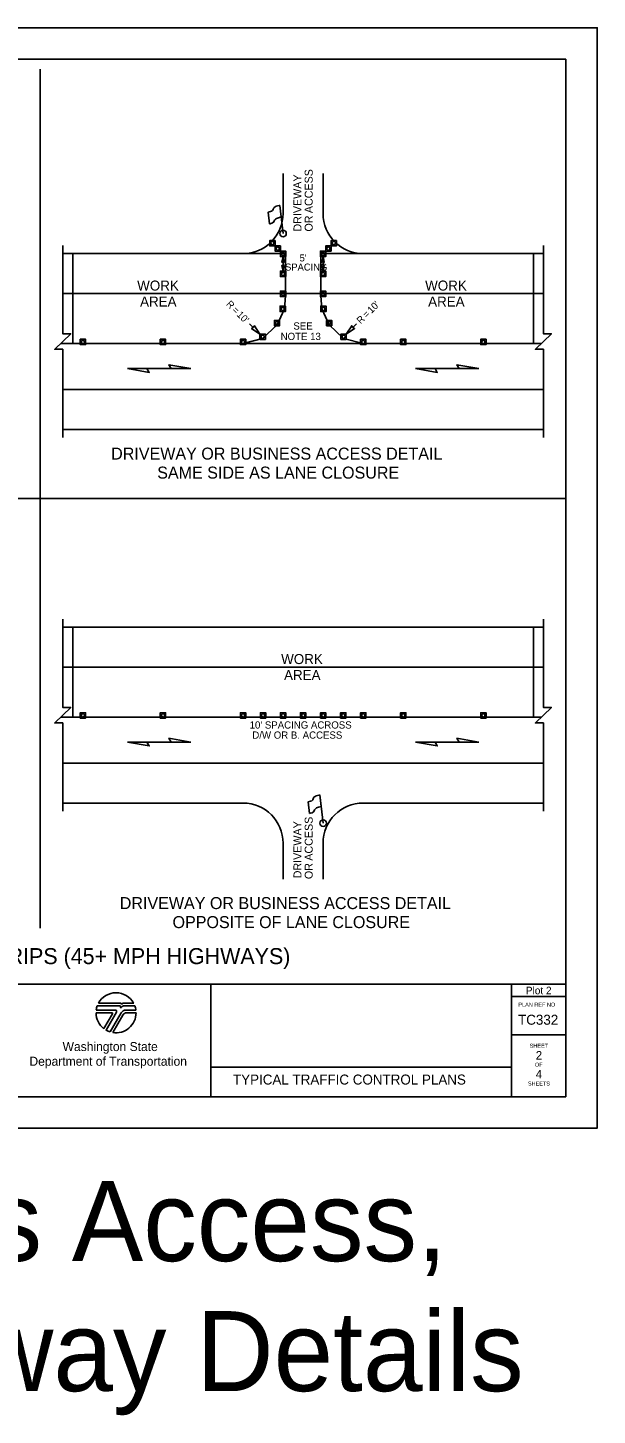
# Model space of a CAD drawing. Extents: x 99999.1 to 100095.7, y 99995 to 100010.7.
# Drawn here: x 100030.38 to 100036.06, y 99996.82 to 100010.69 of the extents above; entities that cross this region are included whole.
import ezdxf

# ---------------------------------------------------------------- set-up
doc = ezdxf.new("R2010")
doc.units = 0
for name, color, linetype in [('RD_ED_DrivewayEdge', 7, 'Continuous'), ('RD_ED_ShoulderPavedEdge', 7, 'Continuous'), ('RD_MK_LineEdgeWhite', 7, 'Continuous'), ('RD_MK_LineSkipCenter', 7, 'Continuous'), ('SH_DE_DetailHeading1Text', 7, 'Continuous'), ('SH_DE_DetailHeading2Text', 7, 'Continuous'), ('SH_GI_PlotLimits', 7, 'Continuous'), ('SH_GI_SheetBorder', 7, 'Continuous'), ('SH_GI_SheetLocationText', 7, 'Continuous'), ('SH_GI_SheetTextInCells', 7, 'Continuous'), ('SH_GI_TitleBlockText', 7, 'Continuous'), ('SH_GI_WSDOTLogo', 7, 'Continuous'), ('TR_WZ_FlaggingStation', 7, 'Continuous'), ('TR_WZ_TrafficCone', 7, 'Continuous'), ('TR_WZ_WorkAreaLabel', 7, 'Continuous'), ('TR_WZ_WorkZoneDetails', 7, 'Continuous'), ('TR_WZ_WorkZoneTextCurrent', 7, 'Continuous')]:
    doc.layers.add(name, color=color, linetype=linetype)

msp = doc.modelspace()

# ---------------------------------------------------------------- linework, layer by layer
at = {"layer": 'RD_ED_DrivewayEdge'}
for p, q in [((100032.925, 100008.83), (100032.925, 100009.23)), ((100033.325, 100008.83), (100033.325, 100009.23)), ((100032.925, 100002.536), (100032.925, 100002.176)), ((100033.325, 100002.536), (100033.325, 100002.176))]:
    msp.add_line(p, q, dxfattribs=at)
for centre, start, end in [((100032.525, 100008.83), 270, 0), ((100033.725, 100008.83), 180, 270), ((100032.525, 100002.536), 0, 90), ((100033.725, 100002.536), 90, 180)]:
    msp.add_arc(centre, 0.4, start, end, dxfattribs=at)
at = {"layer": 'RD_ED_ShoulderPavedEdge'}
for p, q in [((100030.725, 100008.43), (100032.525, 100008.43)), ((100033.725, 100008.43), (100035.525, 100008.43)), ((100030.725, 100006.67), (100035.525, 100006.67)), ((100030.725, 100004.696), (100035.525, 100004.696)), ((100030.725, 100002.936), (100032.525, 100002.936)), ((100033.725, 100002.936), (100035.525, 100002.936))]:
    msp.add_line(p, q, dxfattribs=at)
at = {"layer": 'RD_MK_LineEdgeWhite'}
for p, q in [((100030.725, 100008.03), (100035.525, 100008.03)), ((100030.725, 100007.07), (100035.525, 100007.07)), ((100030.725, 100004.296), (100035.525, 100004.296)), ((100030.725, 100003.336), (100035.525, 100003.336))]:
    msp.add_line(p, q, dxfattribs=at)
at = {"layer": 'RD_MK_LineSkipCenter'}
for points in [[(100035.504, 100007.53), (100030.704, 100007.53)], [(100035.504, 100003.796), (100030.704, 100003.796)]]:
    msp.add_lwpolyline(points, dxfattribs=at)
at = {"layer": 'SH_GI_PlotLimits'}
msp.add_lwpolyline([(100019.062, 99999.687), (100036.062, 99999.687), (100036.062, 100010.687), (100019.062, 100010.687)], close=True, dxfattribs=at)
at = {"layer": 'SH_GI_SheetBorder'}
for p, q in [((100020, 100010.375), (100035.75, 100010.375)), ((100035.75, 100010.375), (100035.75, 100000)), ((100020, 100001.126), (100035.75, 100001.126)), ((100032.205, 100001.126), (100032.205, 100000)), ((100035.208, 100001.126), (100035.208, 100000)), ((100035.208, 100001.001), (100035.75, 100001.001)), ((100035.208, 100000.618), (100035.75, 100000.618)), ((100032.205, 100000.295), (100035.208, 100000.295)), ((100020, 100000), (100035.75, 100000))]:
    msp.add_line(p, q, dxfattribs=at)
at = {"layer": 'SH_GI_WSDOTLogo'}
for p, q in [((100031.059, 100000.866), (100031.25, 100000.866)), ((100031.289, 100000.909), (100031.07, 100000.909)), ((100031.303, 100000.935), (100031.081, 100000.935)), ((100031.433, 100000.935), (100031.335, 100000.935)), ((100031.445, 100000.909), (100031.343, 100000.909)), ((100031.343, 100000.909), (100031.343, 100000.909)), ((100031.356, 100000.866), (100031.456, 100000.866)), ((100031.057, 100000.84), (100031.215, 100000.84)), ((100031.222, 100000.828), (100031.136, 100000.681)), ((100031.261, 100000.846), (100031.157, 100000.667)), ((100031.199, 100000.649), (100031.309, 100000.839)), ((100031.224, 100000.643), (100031.324, 100000.816)), ((100031.365, 100000.839), (100031.457, 100000.839))]:
    msp.add_line(p, q, dxfattribs=at)
for centre, radius, start, end in [((100031.257, 100000.84), 0.2, 28.4787, 151.532), ((100031.257, 100000.84), 0.2, 159.696, 172.5057), ((100031.25, 100000.853), 0.0131, 329.7683, 90), ((100031.289, 100000.895), 0.0148, 327.8418, 89.9985), ((100031.343, 100000.861), 0.0484, 89.9953, 147.8238), ((100031.303, 100000.926), 0.00903, 329.8742, 90.0033), ((100031.356, 100000.812), 0.0542, 90, 149.9974), ((100031.335, 100000.907), 0.0287, 90.0072, 148.1676), ((100031.257, 100000.84), 0.2, 7.4943, 20.2941), ((100031.257, 100000.84), 0.2, 179.9986, 232.8433), ((100031.215, 100000.832), 0.0082, 329.7436, 90), ((100031.257, 100000.84), 0.2, 260.5455, 359.8086), ((100031.365, 100000.792), 0.0476, 90, 150.0543), ((100031.257, 100000.84), 0.2, 239.7929, 253.0448)]:
    msp.add_arc(centre, radius, start, end, dxfattribs=at)
at = {"layer": 'TR_WZ_FlaggingStation'}
for p, q in [((100032.906, 100008.797), (100032.893, 100008.912)), ((100032.925, 100008.63), (100032.893, 100008.911)), ((100032.775, 100008.844), (100032.788, 100008.727)), ((100032.906, 100008.797), (100032.906, 100008.797)), ((100033.175, 100002.949), (100033.188, 100002.832)), ((100033.325, 100002.736), (100033.293, 100003.017)), ((100033.306, 100002.903), (100033.293, 100003.017)), ((100033.306, 100002.903), (100033.306, 100002.903))]:
    msp.add_line(p, q, dxfattribs=at)
for points in [[(100032.893, 100008.912), (100032.887, 100008.91), (100032.869, 100008.907), (100032.856, 100008.903), (100032.846, 100008.897), (100032.837, 100008.892), (100032.832, 100008.885), (100032.827, 100008.877), (100032.827, 100008.871), (100032.821, 100008.862), (100032.811, 100008.854), (100032.798, 100008.849), (100032.775, 100008.844)], [(100032.788, 100008.727), (100032.796, 100008.728), (100032.814, 100008.733), (100032.83, 100008.743), (100032.836, 100008.754), (100032.84, 100008.764), (100032.849, 100008.775), (100032.86, 100008.781), (100032.878, 100008.788), (100032.906, 100008.797)], [(100033.293, 100003.017), (100033.287, 100003.016), (100033.269, 100003.012), (100033.256, 100003.008), (100033.246, 100003.002), (100033.237, 100002.997), (100033.232, 100002.991), (100033.227, 100002.983), (100033.227, 100002.977), (100033.221, 100002.967), (100033.211, 100002.96), (100033.198, 100002.955), (100033.175, 100002.949)], [(100033.188, 100002.832), (100033.196, 100002.834), (100033.214, 100002.838), (100033.23, 100002.849), (100033.236, 100002.859), (100033.24, 100002.87), (100033.249, 100002.88), (100033.26, 100002.887), (100033.278, 100002.894), (100033.306, 100002.903)]]:
    msp.add_lwpolyline(points, dxfattribs=at)
for centre in [(100032.925, 100008.63), (100033.325, 100002.736)]:
    msp.add_circle(centre, 0.0325, dxfattribs=at)
at = {"layer": 'TR_WZ_TrafficCone'}
for points in [[(100032.845, 100008.56), (100032.845, 100008.507), (100032.792, 100008.507), (100032.792, 100008.56), (100032.845, 100008.56)], [(100032.792, 100008.56), (100032.792, 100008.507), (100032.845, 100008.507), (100032.845, 100008.56), (100032.792, 100008.56)], [(100032.898, 100008.507), (100032.898, 100008.454), (100032.845, 100008.454), (100032.845, 100008.507), (100032.898, 100008.507)], [(100032.845, 100008.507), (100032.845, 100008.454), (100032.898, 100008.454), (100032.898, 100008.507), (100032.845, 100008.507)], [(100033.352, 100008.507), (100033.352, 100008.454), (100033.405, 100008.454), (100033.405, 100008.507), (100033.352, 100008.507)], [(100033.405, 100008.507), (100033.405, 100008.454), (100033.352, 100008.454), (100033.352, 100008.507), (100033.405, 100008.507)], [(100033.405, 100008.56), (100033.405, 100008.507), (100033.458, 100008.507), (100033.458, 100008.56), (100033.405, 100008.56)], [(100033.458, 100008.56), (100033.458, 100008.507), (100033.405, 100008.507), (100033.405, 100008.56), (100033.458, 100008.56)], [(100032.898, 100008.454), (100032.952, 100008.454), (100032.952, 100008.4), (100032.898, 100008.4), (100032.898, 100008.454)], [(100032.898, 100008.4), (100032.952, 100008.4), (100032.952, 100008.454), (100032.898, 100008.454), (100032.898, 100008.4)], [(100033.352, 100008.454), (100033.298, 100008.454), (100033.298, 100008.4), (100033.352, 100008.4), (100033.352, 100008.454)], [(100033.352, 100008.4), (100033.298, 100008.4), (100033.298, 100008.454), (100033.352, 100008.454), (100033.352, 100008.4)], [(100032.898, 100008.254), (100032.952, 100008.254), (100032.952, 100008.2), (100032.898, 100008.2), (100032.898, 100008.254)], [(100032.898, 100008.2), (100032.952, 100008.2), (100032.952, 100008.254), (100032.898, 100008.254), (100032.898, 100008.2)], [(100033.352, 100008.254), (100033.298, 100008.254), (100033.298, 100008.2), (100033.352, 100008.2), (100033.352, 100008.254)], [(100033.352, 100008.2), (100033.298, 100008.2), (100033.298, 100008.254), (100033.352, 100008.254), (100033.352, 100008.2)], [(100032.898, 100008.054), (100032.952, 100008.054), (100032.952, 100008), (100032.898, 100008), (100032.898, 100008.054)], [(100032.898, 100008), (100032.952, 100008), (100032.952, 100008.054), (100032.898, 100008.054), (100032.898, 100008)], [(100033.352, 100008.054), (100033.298, 100008.054), (100033.298, 100008), (100033.352, 100008), (100033.352, 100008.054)], [(100033.352, 100008), (100033.298, 100008), (100033.298, 100008.054), (100033.352, 100008.054), (100033.352, 100008)], [(100032.896, 100007.904), (100032.949, 100007.904), (100032.949, 100007.85), (100032.896, 100007.85), (100032.896, 100007.904)], [(100032.896, 100007.85), (100032.949, 100007.85), (100032.949, 100007.904), (100032.896, 100007.904), (100032.896, 100007.85)], [(100033.354, 100007.904), (100033.301, 100007.904), (100033.301, 100007.85), (100033.354, 100007.85), (100033.354, 100007.904)], [(100033.354, 100007.85), (100033.301, 100007.85), (100033.301, 100007.904), (100033.354, 100007.904), (100033.354, 100007.85)], [(100032.838, 100007.762), (100032.891, 100007.762), (100032.891, 100007.708), (100032.838, 100007.708), (100032.838, 100007.762)], [(100032.838, 100007.708), (100032.891, 100007.708), (100032.891, 100007.762), (100032.838, 100007.762), (100032.838, 100007.708)], [(100033.412, 100007.762), (100033.359, 100007.762), (100033.359, 100007.708), (100033.412, 100007.708), (100033.412, 100007.762)], [(100033.412, 100007.708), (100033.359, 100007.708), (100033.359, 100007.762), (100033.412, 100007.762), (100033.412, 100007.708)], [(100030.899, 100007.574), (100030.952, 100007.574), (100030.952, 100007.52), (100030.899, 100007.52), (100030.899, 100007.574)], [(100030.899, 100007.52), (100030.952, 100007.52), (100030.952, 100007.574), (100030.899, 100007.574), (100030.899, 100007.52)], [(100031.699, 100007.574), (100031.752, 100007.574), (100031.752, 100007.52), (100031.699, 100007.52), (100031.699, 100007.574)], [(100031.699, 100007.52), (100031.752, 100007.52), (100031.752, 100007.574), (100031.699, 100007.574), (100031.699, 100007.52)], [(100032.499, 100007.574), (100032.552, 100007.574), (100032.552, 100007.52), (100032.499, 100007.52), (100032.499, 100007.574)], [(100032.499, 100007.52), (100032.552, 100007.52), (100032.552, 100007.574), (100032.499, 100007.574), (100032.499, 100007.52)], [(100032.694, 100007.625), (100032.748, 100007.625), (100032.748, 100007.571), (100032.694, 100007.571), (100032.694, 100007.625)], [(100032.694, 100007.571), (100032.748, 100007.571), (100032.748, 100007.625), (100032.694, 100007.625), (100032.694, 100007.571)], [(100033.556, 100007.625), (100033.502, 100007.625), (100033.502, 100007.571), (100033.556, 100007.571), (100033.556, 100007.625)], [(100033.556, 100007.571), (100033.502, 100007.571), (100033.502, 100007.625), (100033.556, 100007.625), (100033.556, 100007.571)], [(100033.699, 100007.574), (100033.752, 100007.574), (100033.752, 100007.52), (100033.699, 100007.52), (100033.699, 100007.574)], [(100033.699, 100007.52), (100033.752, 100007.52), (100033.752, 100007.574), (100033.699, 100007.574), (100033.699, 100007.52)], [(100034.099, 100007.574), (100034.152, 100007.574), (100034.152, 100007.52), (100034.099, 100007.52), (100034.099, 100007.574)], [(100034.099, 100007.52), (100034.152, 100007.52), (100034.152, 100007.574), (100034.099, 100007.574), (100034.099, 100007.52)], [(100034.899, 100007.574), (100034.952, 100007.574), (100034.952, 100007.52), (100034.899, 100007.52), (100034.899, 100007.574)], [(100034.899, 100007.52), (100034.952, 100007.52), (100034.952, 100007.574), (100034.899, 100007.574), (100034.899, 100007.52)], [(100030.899, 100003.839), (100030.952, 100003.839), (100030.952, 100003.786), (100030.899, 100003.786), (100030.899, 100003.839)], [(100030.899, 100003.786), (100030.952, 100003.786), (100030.952, 100003.839), (100030.899, 100003.839), (100030.899, 100003.786)], [(100031.699, 100003.839), (100031.752, 100003.839), (100031.752, 100003.786), (100031.699, 100003.786), (100031.699, 100003.839)], [(100031.699, 100003.786), (100031.752, 100003.786), (100031.752, 100003.839), (100031.699, 100003.839), (100031.699, 100003.786)], [(100032.499, 100003.839), (100032.552, 100003.839), (100032.552, 100003.786), (100032.499, 100003.786), (100032.499, 100003.839)], [(100032.499, 100003.786), (100032.552, 100003.786), (100032.552, 100003.839), (100032.499, 100003.839), (100032.499, 100003.786)], [(100032.699, 100003.839), (100032.752, 100003.839), (100032.752, 100003.786), (100032.699, 100003.786), (100032.699, 100003.839)], [(100032.699, 100003.786), (100032.752, 100003.786), (100032.752, 100003.839), (100032.699, 100003.839), (100032.699, 100003.786)], [(100032.899, 100003.839), (100032.952, 100003.839), (100032.952, 100003.786), (100032.899, 100003.786), (100032.899, 100003.839)], [(100032.899, 100003.786), (100032.952, 100003.786), (100032.952, 100003.839), (100032.899, 100003.839), (100032.899, 100003.786)], [(100033.099, 100003.839), (100033.152, 100003.839), (100033.152, 100003.786), (100033.099, 100003.786), (100033.099, 100003.839)], [(100033.099, 100003.786), (100033.152, 100003.786), (100033.152, 100003.839), (100033.099, 100003.839), (100033.099, 100003.786)], [(100033.299, 100003.839), (100033.352, 100003.839), (100033.352, 100003.786), (100033.299, 100003.786), (100033.299, 100003.839)], [(100033.299, 100003.786), (100033.352, 100003.786), (100033.352, 100003.839), (100033.299, 100003.839), (100033.299, 100003.786)], [(100033.499, 100003.839), (100033.552, 100003.839), (100033.552, 100003.786), (100033.499, 100003.786), (100033.499, 100003.839)], [(100033.499, 100003.786), (100033.552, 100003.786), (100033.552, 100003.839), (100033.499, 100003.839), (100033.499, 100003.786)], [(100033.699, 100003.839), (100033.752, 100003.839), (100033.752, 100003.786), (100033.699, 100003.786), (100033.699, 100003.839)], [(100033.699, 100003.786), (100033.752, 100003.786), (100033.752, 100003.839), (100033.699, 100003.839), (100033.699, 100003.786)], [(100034.099, 100003.839), (100034.152, 100003.839), (100034.152, 100003.786), (100034.099, 100003.786), (100034.099, 100003.839)], [(100034.099, 100003.786), (100034.152, 100003.786), (100034.152, 100003.839), (100034.099, 100003.839), (100034.099, 100003.786)], [(100034.899, 100003.839), (100034.952, 100003.839), (100034.952, 100003.786), (100034.899, 100003.786), (100034.899, 100003.839)], [(100034.899, 100003.786), (100034.952, 100003.786), (100034.952, 100003.839), (100034.899, 100003.839), (100034.899, 100003.786)]]:
    msp.add_lwpolyline(points, dxfattribs=at)
for centre in [(100032.818, 100008.534), (100032.872, 100008.48), (100033.378, 100008.48), (100033.432, 100008.534), (100032.925, 100008.427), (100033.325, 100008.427), (100032.925, 100008.227), (100033.325, 100008.227), (100032.925, 100008.027), (100033.325, 100008.027), (100032.922, 100007.877), (100033.328, 100007.877), (100032.865, 100007.735), (100033.385, 100007.735), (100030.926, 100007.547), (100031.726, 100007.547), (100032.526, 100007.547), (100032.721, 100007.598), (100033.529, 100007.598), (100033.726, 100007.547), (100034.126, 100007.547), (100034.926, 100007.547), (100030.926, 100003.813), (100031.726, 100003.813), (100032.526, 100003.813), (100032.726, 100003.813), (100032.926, 100003.813), (100033.126, 100003.813), (100033.326, 100003.813), (100033.526, 100003.813), (100033.726, 100003.813), (100034.126, 100003.813), (100034.926, 100003.813)]:
    msp.add_circle(centre, 0.0167, dxfattribs=at)
at = {"layer": 'TR_WZ_WorkZoneDetails'}
for p, q in [((100030.5, 100010.275), (100030.5, 100001.686)), ((100032.925, 100008.346), (100032.925, 100008.308)), ((100033.325, 100008.346), (100033.325, 100008.308)), ((100032.628, 100007.691), (100032.59, 100007.729)), ((100033.622, 100007.691), (100033.66, 100007.729)), ((100031.566, 100007.28), (100031.808, 100007.28)), ((100031.808, 100007.28), (100031.566, 100007.28)), ((100034.443, 100007.28), (100034.684, 100007.28)), ((100034.684, 100007.28), (100034.443, 100007.28)), ((100030.5, 100005.98), (100025.25, 100005.98)), ((100035.75, 100005.98), (100030.5, 100005.98)), ((100031.566, 100003.546), (100031.808, 100003.546)), ((100031.808, 100003.546), (100031.566, 100003.546)), ((100034.443, 100003.546), (100034.684, 100003.546)), ((100034.684, 100003.546), (100034.443, 100003.546))]:
    msp.add_line(p, q, dxfattribs=at)
for points in [[(100030.725, 100006.59), (100030.725, 100007.473), (100030.645, 100007.473), (100030.805, 100007.628), (100030.725, 100007.628), (100030.725, 100008.51)], [(100035.525, 100006.59), (100035.525, 100007.473), (100035.445, 100007.473), (100035.605, 100007.628), (100035.525, 100007.628), (100035.525, 100008.51)], [(100030.725, 100002.856), (100030.725, 100003.738), (100030.645, 100003.738), (100030.805, 100003.893), (100030.725, 100003.893), (100030.725, 100004.776)], [(100035.525, 100002.856), (100035.525, 100003.738), (100035.445, 100003.738), (100035.605, 100003.893), (100035.525, 100003.893), (100035.525, 100004.776)]]:
    msp.add_lwpolyline(points, dxfattribs=at)
for points in [[(100032.948, 100008.43), (100032.948, 100008.207), (100032.948, 100008.007), (100032.939, 100007.877), (100032.939, 100007.877), (100032.939, 100007.877), (100032.865, 100007.718), (100032.865, 100007.718), (100032.865, 100007.718), (100032.721, 100007.581), (100032.526, 100007.53), (100031.529, 100007.53), (100030.949, 100007.53), (100030.825, 100007.53), (100030.825, 100008.43)], [(100032.925, 100008.4), (100032.936, 100008.343), (100032.925, 100008.346), (100032.914, 100008.343)], [(100035.425, 100008.43), (100035.425, 100008.03), (100035.425, 100007.53), (100034.501, 100007.53), (100034.501, 100007.53), (100034.501, 100007.53), (100033.726, 100007.53), (100033.726, 100007.53), (100033.726, 100007.53), (100033.529, 100007.581), (100033.385, 100007.718), (100033.311, 100007.877), (100033.302, 100008.007), (100033.302, 100008.207), (100033.302, 100008.43)], [(100033.325, 100008.4), (100033.336, 100008.343), (100033.325, 100008.346), (100033.314, 100008.343)], [(100032.925, 100008.254), (100032.936, 100008.311), (100032.925, 100008.308), (100032.914, 100008.311)], [(100033.325, 100008.254), (100033.336, 100008.311), (100033.325, 100008.308), (100033.314, 100008.311)], [(100032.694, 100007.625), (100032.611, 100007.681), (100032.628, 100007.691), (100032.639, 100007.708)], [(100033.556, 100007.625), (100033.639, 100007.681), (100033.622, 100007.691), (100033.611, 100007.708)], [(100031.37, 100007.28), (100031.589, 100007.242), (100031.566, 100007.28)], [(100032.004, 100007.28), (100031.785, 100007.319), (100031.808, 100007.28)], [(100034.247, 100007.28), (100034.465, 100007.242), (100034.443, 100007.28)], [(100034.881, 100007.28), (100034.662, 100007.319), (100034.684, 100007.28)], [(100030.825, 100004.696), (100030.825, 100003.796), (100035.425, 100003.796), (100035.425, 100004.696)], [(100031.37, 100003.546), (100031.589, 100003.507), (100031.566, 100003.546)], [(100032.004, 100003.546), (100031.785, 100003.584), (100031.808, 100003.546)], [(100034.247, 100003.546), (100034.465, 100003.507), (100034.443, 100003.546)], [(100034.881, 100003.546), (100034.662, 100003.584), (100034.684, 100003.546)]]:
    msp.add_lwpolyline(points, close=True, dxfattribs=at)

# ---------------------------------------------------------------- texts
at = {"layer": 'SH_DE_DetailHeading1Text'}
msp.add_text('ALTERNATING 1-LANE, 2-WAY TRAFFIC: AFAD-CONTROLLED + TEMP. RUMBLE STRIPS (45+ MPH HIGHWAYS)', height=0.16, rotation=360, dxfattribs=at).set_placement((100021.704, 100001.326))
at = {"layer": 'SH_DE_DetailHeading2Text'}
for s, p in [('DRIVEWAY OR BUSINESS ACCESS DETAIL', (100031.208, 100006.37)), ('SAME SIDE AS LANE CLOSURE', (100031.668, 100006.18)), ('DRIVEWAY OR BUSINESS ACCESS DETAIL', (100031.294, 100001.876)), ('OPPOSITE OF LANE CLOSURE', (100031.821, 100001.686))]:
    msp.add_text(s, height=0.12, rotation=360, dxfattribs=at).set_placement(p)
at = {"layer": 'SH_GI_SheetBorder'}
msp.add_text('PLAN REF NO', height=0.04003, dxfattribs=at).set_placement((100035.275, 100000.901))
at = {"layer": 'SH_GI_SheetLocationText'}
for s, height, p in [('Plot 2', 0.075, (100035.35, 100001.025)), ('Driveway, Business Access,', 0.8, (100021.184, 99998.357)), ('or Intersecting Roadway Details', 0.8, (100020.225, 99997.057))]:
    msp.add_text(s, height=height, dxfattribs=at).set_placement(p)
at = {"layer": 'SH_GI_SheetTextInCells'}
for s, height, p in [('Washington State', 0.09007, (100030.723, 100000.457)), ('SHEET', 0.04, (100035.388, 100000.49)), ('Department of Transportation', 0.09007, (100030.392, 100000.31)), ('OF', 0.04, (100035.441, 100000.301)), ('SHEETS', 0.04, (100035.37, 100000.112))]:
    msp.add_text(s, height=height, dxfattribs=at).set_placement(p)
at = {"layer": 'SH_GI_TitleBlockText'}
for s, height, p in [('TC332', 0.1, (100035.272, 100000.72)), ('2', 0.085, (100035.449, 100000.372)), ('TYPICAL TRAFFIC CONTROL PLANS', 0.1, (100032.425, 100000.122)), ('4', 0.085, (100035.449, 100000.184))]:
    msp.add_text(s, height=height, dxfattribs=at).set_placement(p)
at = {"layer": 'TR_WZ_WorkAreaLabel'}
for s, p in [('WORK', (100031.468, 100008.06)), ('WORK', (100034.344, 100008.06)), ('AREA', (100031.497, 100007.9)), ('AREA', (100034.374, 100007.9)), ('WORK', (100032.906, 100004.326)), ('AREA', (100032.935, 100004.166))]:
    msp.add_text(s, height=0.1, dxfattribs=at).set_placement(p)
at = {"layer": 'TR_WZ_WorkZoneTextCurrent'}
for s, height, rotation, p in [('DRIVEWAY', 0.08, 90, (100033.109, 100008.65)), ('ACCESS', 0.08, 90, (100033.221, 100008.834)), ('OR', 0.08, 90, (100033.221, 100008.65)), ('R', 0.07, 315, (100032.351, 100007.919)), ("10'", 0.07, 45, (100033.808, 100007.827)), ('=', 0.07, 315, (100032.41, 100007.859)), ("10'", 0.07, 315, (100032.457, 100007.813)), ('R', 0.07, 45, (100033.701, 100007.721)), ('=', 0.07, 45, (100033.761, 100007.78)), ('ACCESS', 0.08, 90, (100033.221, 100002.36)), ('DRIVEWAY', 0.08, 90, (100033.109, 100002.184)), ('OR', 0.08, 90, (100033.221, 100002.176))]:
    msp.add_text(s, height=height, rotation=rotation, dxfattribs=at).set_placement(p)
for s, height, p in [("5'", 0.07, (100033.09, 100008.351)), ('SPACING', 0.07, (100032.945, 100008.26)), ('SEE', 0.072, (100033.028, 100007.67)), ('NOTE 13', 0.072, (100032.901, 100007.566)), ("10' SPACING ACROSS", 0.072, (100032.591, 100003.681)), ('D/W OR B. ACCESS', 0.072, (100032.618, 100003.58))]:
    msp.add_text(s, height=height, dxfattribs=at).set_placement(p)

doc.saveas('drawing.dxf')
